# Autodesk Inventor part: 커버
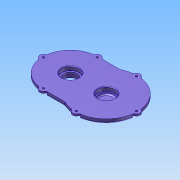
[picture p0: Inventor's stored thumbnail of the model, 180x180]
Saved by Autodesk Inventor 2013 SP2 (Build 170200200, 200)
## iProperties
Created: 2025-09
Part Number: 커버
Material: Generic
Document SubType Name: Modeling
Designer: a
Density: 1 g/cm^3
Author: a
변환 표준: STEP AP214IS
전처리기: Build: 200, Release: 2013 SP2 Update 6 - Date: Thu 07/17/2014
전송 단위: 밀리미터
불확실성: 0.01
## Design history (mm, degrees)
node "커버1"
node "솔리드1"
node "기준1"
